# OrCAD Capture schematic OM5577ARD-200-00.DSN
size A4; title: .; rev: 00; note: Arduino Interface Board
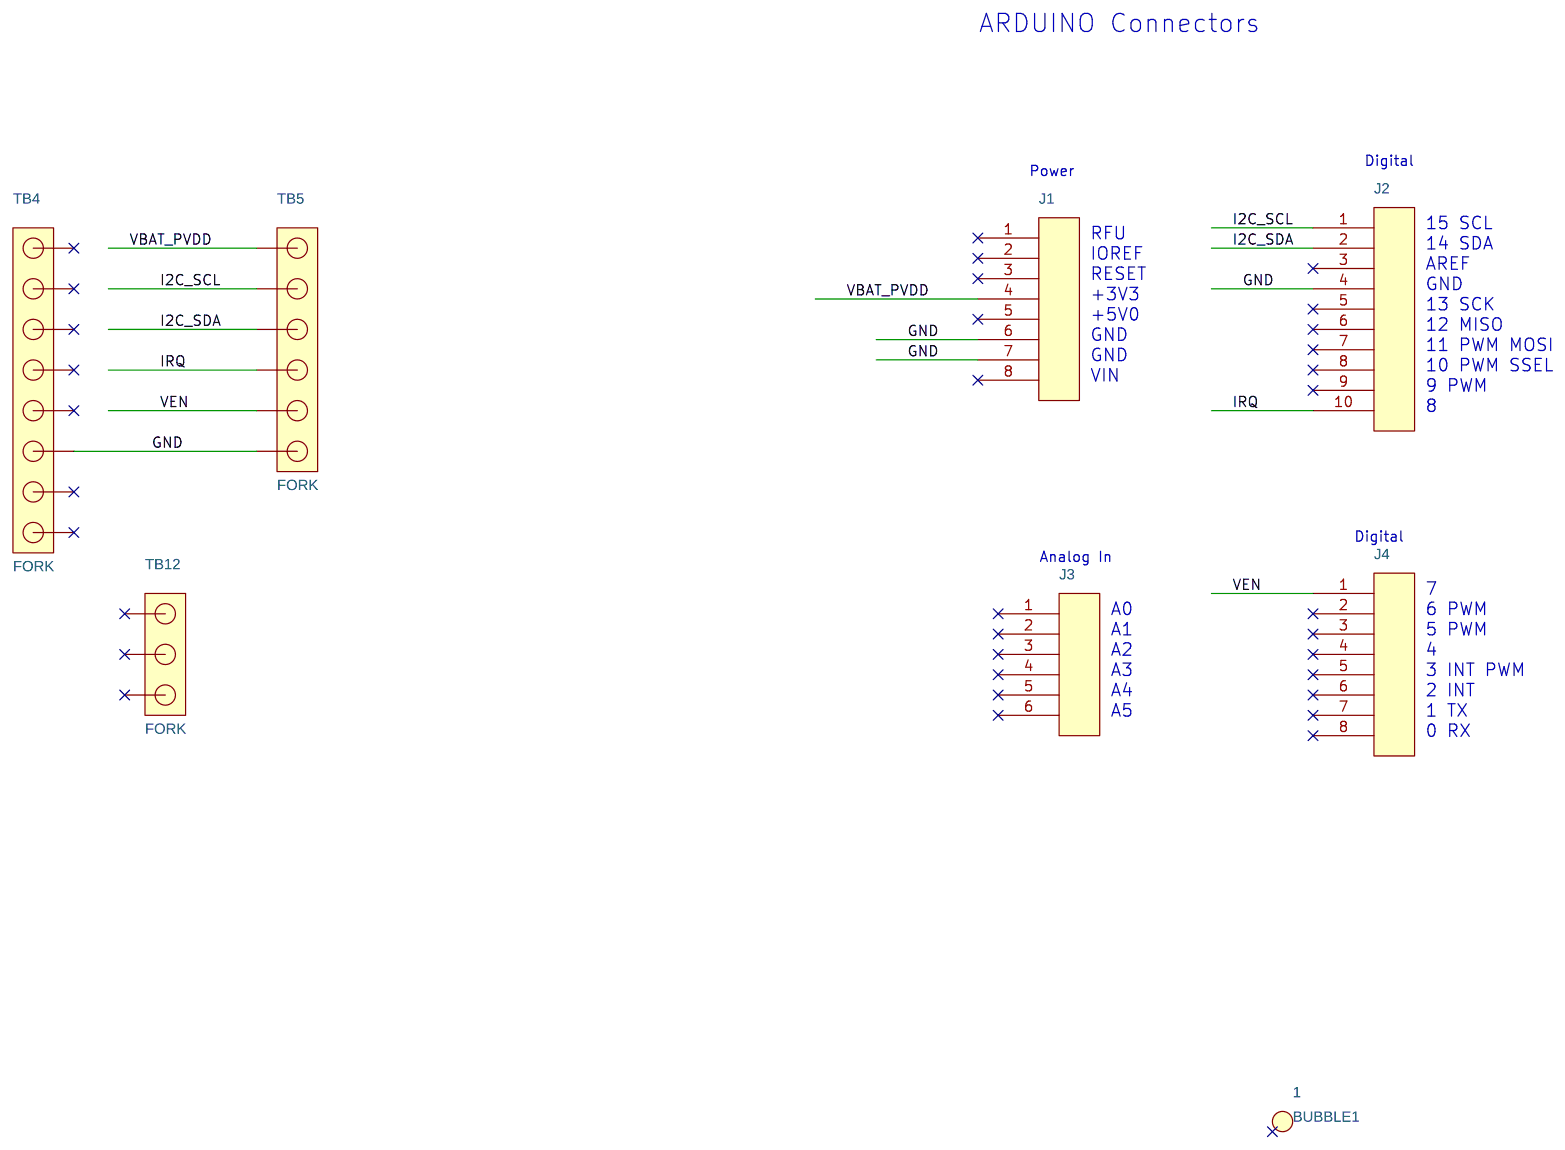
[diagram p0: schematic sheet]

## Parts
1  BUBBLE1  [BUBBLE_DIAM8]
J1  Con 1 x 8  [con_bar_254_8_md]
J2  Con 1 x 10  [con_bar_254_10_md]
J3  Con 1 x 6  [con_bar_254_6_md]
J4  Con 1 x 8  [con_bar_254_8_md]
TB4  FORK  [AGPS1-08-BSE]
TB5  FORK  [AGPS1-06-BSE]
TB12  FORK  [AGPS1-03-BSE]

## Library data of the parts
1 = BUBBLE_CI: Designation: Printed_Circuit_Board:OM5577ARD-00
J1 J4 = Con_1_x_8: Designation: Header, Single Row, pitch 2mm54, 1x8; Manufacturer: SAMTEC; REF.Manufacturer: TSW-108-07-T-S
J2 = Con_1_x_10: Designation: Header, Single Row, pitch 2mm54, 1x10; Manufacturer: SAMTEC; REF.Manufacturer: TSW-110-07-T-S
J3 = Con_1_x_6: Designation: Header, Single Row, pitch 2mm54, 1x6; Manufacturer: SAMTEC; REF.Manufacturer: TSW-106-07-T-S
TB4 = bar_1x8_MD: Designation: Remove Header after soldering; Manufacturer: ANTELEC
TB5 = bar_1x6_MD: Designation: Remove Header after soldering; Manufacturer: ANTELEC
TB12 = bar_1x3_MD: Designation: Remove Header after soldering; Manufacturer: ANTELEC

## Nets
GND: J1.6 J1.7 J2.4 TB4.6 TB5.6
VBAT_PVDD: J1.4 TB5.1
I2C_SCL: J2.1 TB5.2
I2C_SDA: J2.2 TB5.3
IRQ: J2.10 TB5.4
VEN: J4.1 TB5.5

Not connected (* = marked no-connect by the designer): 1 1*; J1 1* 2* 3* 5* 8*; J2 3* 5* 6* 7* 8* 9*; J3 1* 2* 3* 4* 5* 6*; J4 2* 3* 4* 5* 6* 7* 8*; TB4 1* 2* 3* 4* 5* 7* 8*; TB12 1* 2* 3*

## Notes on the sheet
- ARDUINO Connectors
- Power
- Digital
- 15 SCL
- IOREF
- RFU
- 14 SDA
- RESET
- AREF
- +3V3
- GND
- +5V0
- 12 MISO
- 13 SCK
- GND
- 11 PWM MOSI
- GND
- 10 PWM SSEL
- VIN
- 9 PWM
- 8
- Digital
- Analog In
- 7
- A0
- 6 PWM
- A1
- 5 PWM
- A2
- 4
- A3
- 3 INT PWM
- A4
- A5
- 1 TX
- 2 INT
- 0 RX
